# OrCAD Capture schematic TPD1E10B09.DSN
size A; title: TPD1E10B09 Single-Channel ESD Protection; rev: 1.0; note: Datasheet: SLLSEB0
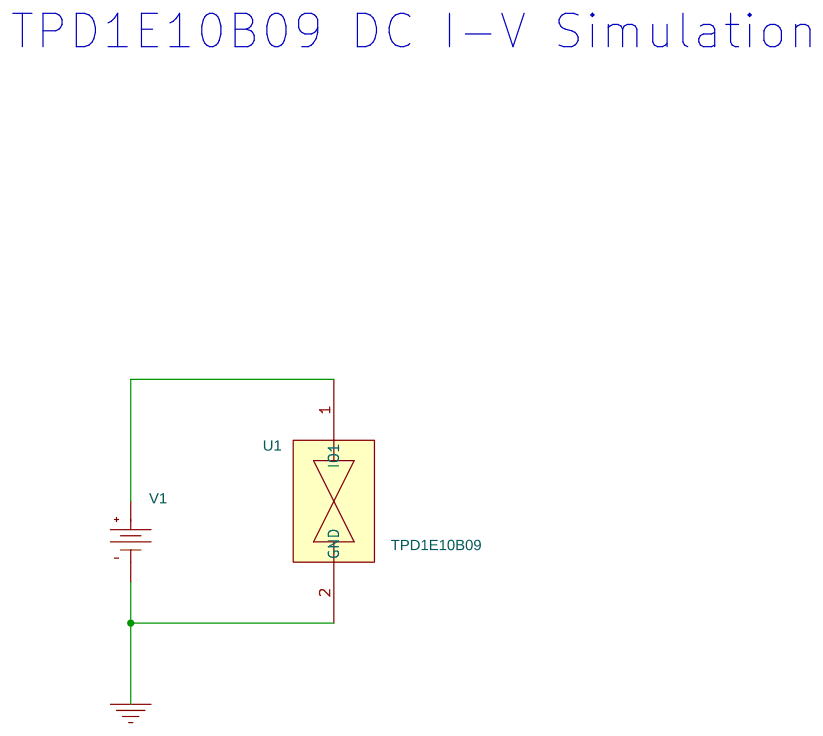
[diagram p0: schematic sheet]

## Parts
U1  TPD1E10B09
V1  VDC

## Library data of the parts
U1 = TPD1E10B09
V1 = VDC

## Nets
0: U1.2(GND) V1.1(-)
N02941: U1.1(IO1) V1.0(+)

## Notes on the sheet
- TPD1E10B09 DC I-V Simulation
